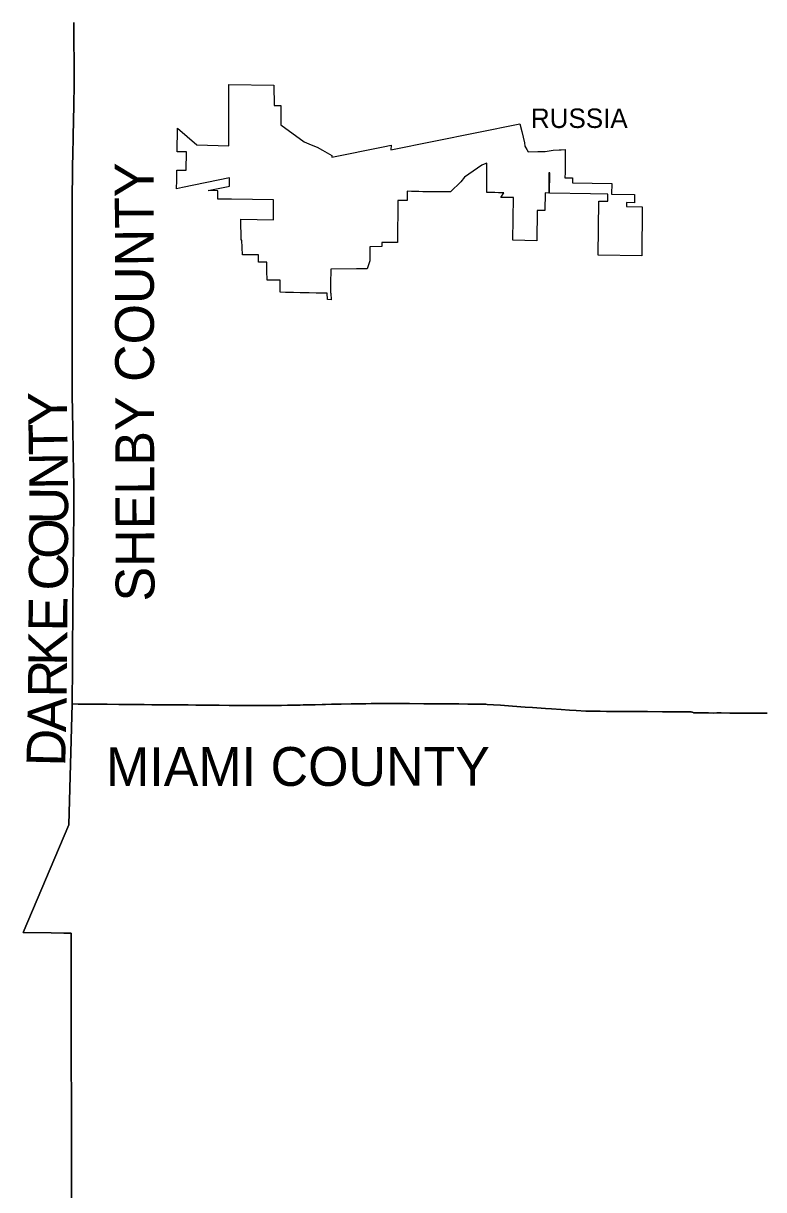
# Model space of a CAD drawing. Extents: x 0 to 34, y 0 to 22.
# Drawn here: x 4.2472 to 4.5535, y 17.5508 to 18.0331 of the extents above; entities that cross this region are included whole.
import ezdxf

# ---------------------------------------------------------------- set-up
doc = ezdxf.new("R2010")
doc.units = 0
for name, color, linetype in [('GM_X_Corporation', 7, 'Continuous'), ('GM_X_Corporation_Text', 7, 'Continuous'), ('GM_X_County', 7, 'Continuous'), ('GM_X_County_Text', 7, 'Continuous')]:
    doc.layers.add(name, color=color, linetype=linetype)

msp = doc.modelspace()

# ---------------------------------------------------------------- linework, layer by layer
at = {"layer": 'GM_X_Corporation'}
for points in [[(4.46487, 17.96282), (4.465, 17.97134), (4.46464, 17.97134), (4.46459, 17.96292), (4.46309, 17.96294), (4.46295, 17.95564), (4.45975, 17.95565), (4.45957, 17.94316), (4.44972, 17.94338), (4.44995, 17.96107), (4.44467, 17.96111), (4.44592, 17.96306), (4.44583, 17.96307), (4.44383, 17.96307), (4.4423, 17.96308), (4.44093, 17.96309), (4.43892, 17.96312), (4.43894, 17.96904), (4.43899, 17.97525), (4.43785, 17.97491), (4.43693, 17.97449), (4.42971, 17.96952), (4.42813, 17.9676), (4.4239, 17.96335), (4.42352, 17.96336), (4.41856, 17.96343), (4.41251, 17.96348), (4.41083, 17.9635), (4.40777, 17.96356), (4.40597, 17.96363), (4.40592, 17.95982), (4.40214, 17.95985), (4.40204, 17.94241), (4.39557, 17.94244), (4.39553, 17.94082), (4.39055, 17.94073), (4.39047, 17.93488), (4.38946, 17.93158), (4.38504, 17.93156), (4.37434, 17.93149), (4.37431, 17.92534), (4.3743, 17.92148), (4.37447, 17.92148), (4.37449, 17.91882), (4.37299, 17.91883), (4.37294, 17.9215), (4.37248, 17.92151), (4.37185, 17.92149), (4.37143, 17.9215), (4.37086, 17.92151), (4.37028, 17.92152), (4.36838, 17.92155), (4.36548, 17.92162), (4.36284, 17.92166), (4.36174, 17.92168), (4.35901, 17.92174), (4.35706, 17.92176), (4.35563, 17.92178), (4.3534, 17.92186), (4.35341, 17.92688), (4.34802, 17.9269), (4.348, 17.93081), (4.348, 17.93439), (4.34444, 17.93438), (4.34444, 17.93734), (4.3378, 17.93732), (4.33766, 17.94336), (4.33727, 17.94337), (4.33719, 17.95216), (4.35065, 17.95182), (4.35067, 17.96008), (4.33325, 17.96034), (4.33249, 17.96035), (4.32766, 17.96041), (4.32765, 17.96388), (4.32368, 17.96392), (4.332, 17.96567), (4.33245, 17.96576), (4.33243, 17.96915), (4.31301, 17.96521), (4.31061, 17.96463), (4.31061, 17.96505), (4.31062, 17.96581), (4.31064, 17.96718), (4.31064, 17.96866), (4.31069, 17.97239), (4.31457, 17.97232), (4.31466, 17.98002), (4.3109, 17.98002), (4.31099, 17.98971), (4.31904, 17.98287), (4.33218, 17.9825), (4.3322, 18.00776), (4.35087, 18.0075), (4.3509, 17.99908), (4.35374, 17.99909), (4.35374, 17.99742), (4.35372, 17.99441), (4.35369, 17.9911), (4.36335, 17.98406), (4.36632, 17.98291), (4.36877, 17.98185), (4.37093, 17.98063), (4.3748, 17.97845), (4.37478, 17.97774), (4.3961, 17.98202), (4.3993, 17.98271), (4.3992, 17.98084), (4.45259, 17.99157), (4.45347, 17.98831), (4.45447, 17.98369), (4.45461, 17.98225), (4.45551, 17.9809), (4.45607, 17.97998), (4.46002, 17.98015), (4.46306, 17.98016), (4.46643, 17.98062), (4.46888, 17.98079), (4.46975, 17.98075), (4.47128, 17.98091), (4.47137, 17.9714), (4.47129, 17.9714), (4.47126, 17.96918), (4.47432, 17.96915), (4.47431, 17.96717), (4.49065, 17.96692), (4.49053, 17.96245), (4.50005, 17.96226), (4.49996, 17.9589), (4.49675, 17.95899), (4.49671, 17.95738), (4.50322, 17.95721), (4.50307, 17.93698), (4.48502, 17.93721), (4.48533, 17.95958), (4.48895, 17.95949), (4.48897, 17.96249), (4.48176, 17.96264)], [(4.46487, 17.96282), (4.46487, 17.96282), (4.46487, 17.96282)]]:
    msp.add_lwpolyline(points, close=True, dxfattribs=at)
at = {"layer": 'GM_X_County'}
for points in [[(4.26805, 18.03349), (4.26805, 18.03186), (4.26807, 18.03033), (4.2681, 18.02933), (4.26813, 18.02801), (4.26814, 18.0269), (4.26812, 18.02432), (4.26813, 18.02269), (4.26819, 18.01995), (4.26824, 18.01721), (4.26825, 18.01589), (4.26828, 18.01141), (4.26829, 18.00876), (4.2683, 18.00835), (4.26826, 18.00587), (4.26814, 18.00123), (4.26807, 17.99801), (4.268, 17.99406), (4.26794, 17.99179), (4.26787, 17.98757), (4.26781, 17.98435), (4.26773, 17.98051), (4.26761, 17.9726), (4.26754, 17.96943), (4.26744, 17.96268), (4.26742, 17.95994), (4.26741, 17.95678), (4.26741, 17.95567), (4.26741, 17.95557), (4.26741, 17.95472), (4.26741, 17.9543), (4.2674, 17.95383), (4.26741, 17.95309), (4.26745, 17.94982), (4.26744, 17.94602), (4.26744, 17.94307), (4.26744, 17.9389), (4.26741, 17.93242), (4.26742, 17.92915), (4.26742, 17.92625), (4.26744, 17.92414), (4.26744, 17.92339), (4.26745, 17.92071), (4.26746, 17.91802), (4.26745, 17.91533), (4.26743, 17.9119), (4.26743, 17.90721), (4.26743, 17.90367), (4.26742, 17.90019), (4.26742, 17.89814), (4.26739, 17.89545), (4.26737, 17.89097), (4.2674, 17.88664), (4.26739, 17.88395), (4.26743, 17.87926), (4.26744, 17.87752), (4.26751, 17.87436), (4.26754, 17.87256), (4.26756, 17.87151), (4.2676, 17.86998), (4.26766, 17.86777), (4.26768, 17.86661), (4.26769, 17.86519), (4.26772, 17.86372), (4.26774, 17.86188), (4.26778, 17.85929), (4.2678, 17.85782), (4.26783, 17.85645), (4.26787, 17.85291), (4.26793, 17.85017), (4.26799, 17.84669), (4.26804, 17.84316), (4.26812, 17.83841), (4.26813, 17.83735), (4.26813, 17.83651), (4.26812, 17.83456), (4.26811, 17.83303), (4.26811, 17.83024), (4.26808, 17.82655), (4.26803, 17.82349), (4.26798, 17.81853), (4.26792, 17.81389), (4.26788, 17.81115), (4.26785, 17.80867), (4.26779, 17.80561), (4.26778, 17.80187), (4.26773, 17.79744), (4.2677, 17.79264), (4.26766, 17.78821), (4.26762, 17.78325), (4.2676, 17.78078), (4.26754, 17.77176), (4.26751, 17.76775), (4.26748, 17.76089), (4.26747, 17.7582), (4.26745, 17.75525), (4.26743, 17.75161), (4.26609, 17.70162), (4.2472, 17.65706), (4.25869, 17.65694), (4.26401, 17.65686), (4.26703, 17.65681), (4.26718, 17.53392)], [(4.55491, 17.74788), (4.55154, 17.74785), (4.54969, 17.74786), (4.54753, 17.74787), (4.54531, 17.74787), (4.54384, 17.74788), (4.53941, 17.74788), (4.53582, 17.74789), (4.53408, 17.74789), (4.53287, 17.74788), (4.53065, 17.74789), (4.52828, 17.7479), (4.52633, 17.74791), (4.5258, 17.74791), (4.525, 17.74796), (4.52463, 17.74799), (4.52458, 17.74799), (4.52441, 17.74802), (4.52426, 17.74808), (4.52403, 17.74818), (4.52397, 17.7482), (4.52367, 17.74828), (4.52342, 17.74832), (4.52311, 17.74833), (4.52249, 17.74836), (4.52175, 17.74836), (4.51869, 17.74838), (4.51463, 17.74841), (4.51157, 17.74841), (4.50535, 17.74846), (4.50208, 17.74848), (4.49939, 17.7485), (4.49733, 17.74851), (4.49317, 17.74855), (4.48842, 17.74856), (4.48578, 17.74858), (4.48352, 17.7486), (4.48135, 17.74865), (4.47984, 17.74871), (4.47587, 17.74893), (4.47308, 17.74911), (4.46972, 17.74932), (4.46572, 17.7496), (4.46319, 17.74977), (4.45783, 17.75015), (4.45477, 17.75035), (4.44962, 17.75073), (4.44452, 17.75109), (4.44163, 17.75131), (4.4391, 17.75146), (4.43854, 17.75148), (4.43805, 17.7515), (4.43694, 17.75151), (4.43668, 17.75152), (4.4361, 17.75152), (4.43436, 17.75154), (4.43357, 17.75157), (4.43267, 17.75157), (4.43183, 17.75158), (4.43104, 17.7516), (4.4274, 17.75162), (4.42677, 17.75162), (4.42566, 17.75162), (4.42471, 17.75162), (4.42318, 17.75164), (4.42287, 17.75162), (4.42255, 17.75163), (4.42234, 17.75162), (4.42187, 17.75164), (4.42103, 17.75165), (4.41902, 17.75162), (4.4177, 17.75163), (4.41518, 17.75168), (4.41286, 17.75169), (4.4069, 17.75178), (4.40136, 17.75181), (4.39983, 17.75179), (4.39756, 17.75182), (4.39514, 17.75182), (4.3924, 17.75179), (4.39108, 17.75177), (4.38887, 17.75173), (4.38681, 17.7517), (4.38454, 17.75168), (4.38285, 17.75165), (4.37864, 17.75155), (4.37653, 17.75152), (4.37474, 17.75149), (4.3722, 17.75142), (4.37089, 17.75141), (4.36794, 17.75133), (4.36619, 17.7513), (4.36293, 17.75122), (4.36172, 17.75118), (4.36156, 17.75116), (4.36114, 17.75116), (4.36072, 17.75114), (4.36062, 17.75114), (4.3602, 17.75115), (4.35651, 17.75106), (4.35404, 17.75099), (4.35309, 17.75095), (4.35286, 17.75095), (4.35208, 17.75094), (4.35034, 17.75094), (4.34913, 17.75093), (4.3448, 17.75095), (4.34154, 17.75099), (4.33832, 17.751), (4.33547, 17.75102), (4.33236, 17.75104), (4.32825, 17.75109), (4.32355, 17.75111), (4.32171, 17.75113), (4.31854, 17.75119), (4.31543, 17.75121), (4.31201, 17.75122), (4.30747, 17.75127), (4.30341, 17.75131), (4.30035, 17.75131), (4.29719, 17.75136), (4.29408, 17.75139), (4.2896, 17.75143), (4.2867, 17.75145), (4.28184, 17.75151), (4.27942, 17.75153), (4.2781, 17.75155), (4.27388, 17.75155), (4.26993, 17.75158), (4.26743, 17.75161), (4.26745, 17.75525), (4.26747, 17.7582), (4.26748, 17.76089), (4.26751, 17.76775), (4.26754, 17.77176), (4.2676, 17.78078), (4.26762, 17.78325), (4.26766, 17.78821), (4.2677, 17.79264), (4.26773, 17.79744), (4.26778, 17.80187), (4.26779, 17.80561), (4.26785, 17.80867), (4.26788, 17.81115), (4.26792, 17.81389), (4.26798, 17.81853), (4.26803, 17.82349), (4.26808, 17.82655), (4.26811, 17.83024), (4.26811, 17.83303), (4.26812, 17.83456), (4.26813, 17.83651), (4.26813, 17.83735), (4.26812, 17.83841), (4.26804, 17.84316), (4.26799, 17.84669), (4.26793, 17.85017), (4.26787, 17.85291), (4.26783, 17.85645), (4.2678, 17.85782), (4.26778, 17.85929), (4.26774, 17.86188), (4.26772, 17.86372), (4.26769, 17.86519), (4.26768, 17.86661), (4.26766, 17.86777), (4.2676, 17.86998), (4.26756, 17.87151), (4.26754, 17.87256), (4.26751, 17.87436), (4.26744, 17.87752), (4.26743, 17.87926), (4.26739, 17.88395), (4.2674, 17.88664), (4.26737, 17.89097), (4.26739, 17.89545), (4.26742, 17.89814), (4.26742, 17.90019), (4.26743, 17.90367), (4.26743, 17.90721), (4.26743, 17.9119), (4.26745, 17.91533), (4.26746, 17.91802), (4.26745, 17.92071), (4.26744, 17.92339), (4.26744, 17.92414), (4.26742, 17.92625), (4.26742, 17.92915), (4.26741, 17.93242), (4.26744, 17.9389), (4.26744, 17.94307), (4.26744, 17.94602), (4.26745, 17.94982), (4.26741, 17.95309), (4.2674, 17.95383), (4.26741, 17.9543), (4.26741, 17.95472), (4.26741, 17.95557), (4.26741, 17.95567), (4.26741, 17.95678), (4.26742, 17.95994), (4.26744, 17.96268), (4.26754, 17.96943), (4.26761, 17.9726), (4.26773, 17.98051), (4.26781, 17.98435), (4.26787, 17.98757), (4.26794, 17.99179), (4.268, 17.99406), (4.26807, 17.99801), (4.26814, 18.00123), (4.26826, 18.00587), (4.2683, 18.00835), (4.26829, 18.00876), (4.26828, 18.01141), (4.26825, 18.01589), (4.26824, 18.01721), (4.26819, 18.01995), (4.26813, 18.02269), (4.26812, 18.02432), (4.26814, 18.0269), (4.26813, 18.02801), (4.2681, 18.02933), (4.26807, 18.03033), (4.26805, 18.03186), (4.26805, 18.03349)], [(4.26718, 17.53392), (4.26703, 17.65681), (4.26401, 17.65686), (4.25869, 17.65694), (4.2472, 17.65706), (4.26609, 17.70162), (4.26743, 17.75161), (4.26993, 17.75158), (4.27388, 17.75155), (4.2781, 17.75155), (4.27942, 17.75153), (4.28184, 17.75151), (4.2867, 17.75145), (4.2896, 17.75143), (4.29408, 17.75139), (4.29719, 17.75136), (4.30035, 17.75131), (4.30341, 17.75131), (4.30747, 17.75127), (4.31201, 17.75122), (4.31543, 17.75121), (4.31854, 17.75119), (4.32171, 17.75113), (4.32355, 17.75111), (4.32825, 17.75109), (4.33236, 17.75104), (4.33547, 17.75102), (4.33832, 17.751), (4.34154, 17.75099), (4.3448, 17.75095), (4.34913, 17.75093), (4.35034, 17.75094), (4.35208, 17.75094), (4.35286, 17.75095), (4.35309, 17.75095), (4.35404, 17.75099), (4.35651, 17.75106), (4.3602, 17.75115), (4.36062, 17.75114), (4.36072, 17.75114), (4.36114, 17.75116), (4.36156, 17.75116), (4.36172, 17.75118), (4.36293, 17.75122), (4.36619, 17.7513), (4.36794, 17.75133), (4.37089, 17.75141), (4.3722, 17.75142), (4.37474, 17.75149), (4.37653, 17.75152), (4.37864, 17.75155), (4.38285, 17.75165), (4.38454, 17.75168), (4.38681, 17.7517), (4.38887, 17.75173), (4.39108, 17.75177), (4.3924, 17.75179), (4.39514, 17.75182), (4.39756, 17.75182), (4.39983, 17.75179), (4.40136, 17.75181), (4.4069, 17.75178), (4.41286, 17.75169), (4.41518, 17.75168), (4.4177, 17.75163), (4.41902, 17.75162), (4.42103, 17.75165), (4.42187, 17.75164), (4.42234, 17.75162), (4.42255, 17.75163), (4.42287, 17.75162), (4.42318, 17.75164), (4.42471, 17.75162), (4.42566, 17.75162), (4.42677, 17.75162), (4.4274, 17.75162), (4.43104, 17.7516), (4.43183, 17.75158), (4.43267, 17.75157), (4.43357, 17.75157), (4.43436, 17.75154), (4.4361, 17.75152), (4.43668, 17.75152), (4.43694, 17.75151), (4.43805, 17.7515), (4.43854, 17.75148), (4.4391, 17.75146), (4.44163, 17.75131), (4.44452, 17.75109), (4.44962, 17.75073), (4.45477, 17.75035), (4.45783, 17.75015), (4.46319, 17.74977), (4.46572, 17.7496), (4.46972, 17.74932), (4.47308, 17.74911), (4.47587, 17.74893), (4.47984, 17.74871), (4.48135, 17.74865), (4.48352, 17.7486), (4.48578, 17.74858), (4.48842, 17.74856), (4.49317, 17.74855), (4.49733, 17.74851), (4.49939, 17.7485), (4.50208, 17.74848), (4.50535, 17.74846), (4.51157, 17.74841), (4.51463, 17.74841), (4.51869, 17.74838), (4.52175, 17.74836), (4.52249, 17.74836), (4.52311, 17.74833), (4.52342, 17.74832), (4.52367, 17.74828), (4.52397, 17.7482), (4.52403, 17.74818), (4.52426, 17.74808), (4.52441, 17.74802), (4.52458, 17.74799), (4.52463, 17.74799), (4.525, 17.74796), (4.5258, 17.74791), (4.52633, 17.74791), (4.52828, 17.7479), (4.53065, 17.74789), (4.53287, 17.74788), (4.53408, 17.74789), (4.53582, 17.74789), (4.53941, 17.74788), (4.54384, 17.74788), (4.54531, 17.74787), (4.54753, 17.74787), (4.54969, 17.74786), (4.55154, 17.74785), (4.55491, 17.74788)]]:
    msp.add_lwpolyline(points, dxfattribs=at)

# ---------------------------------------------------------------- texts
at = {"layer": 'GM_X_Corporation_Text'}
msp.add_text('RUSSIA', height=0.008037, rotation=0, dxfattribs=at).set_placement((4.45718, 17.98983))
at = {"layer": 'GM_X_County_Text'}
for s, height, rotation, p in [('SHELBY COUNTY', 0.016074, 90.1229, (4.30148, 17.79402)), ('Y', 0.01607, 90.854, (4.26539, 17.86655)), ('T', 0.01607, 90.854, (4.26557, 17.85455)), ('N', 0.01607, 90.7817, (4.26576, 17.84034)), ('U', 0.01607, 89.8855, (4.26573, 17.82588)), ('O', 0.01607, 89.5429, (4.26562, 17.81159)), ('C', 0.01607, 89.5426, (4.26552, 17.79848)), ('E', 0.01607, 89.5421, (4.26538, 17.78157)), ('K', 0.01607, 89.5429, (4.26527, 17.76738)), ('R', 0.01607, 89.4812, (4.26515, 17.75426)), ('A', 0.01607, 88.8678, (4.26487, 17.73989)), ('D', 0.01607, 88.6434, (4.26453, 17.72564)), ('MIAMI COUNTY', 0.016074, 0.0537, (4.28141, 17.71766))]:
    msp.add_text(s, height=height, rotation=rotation, dxfattribs=at).set_placement(p)

doc.saveas('drawing.dxf')
